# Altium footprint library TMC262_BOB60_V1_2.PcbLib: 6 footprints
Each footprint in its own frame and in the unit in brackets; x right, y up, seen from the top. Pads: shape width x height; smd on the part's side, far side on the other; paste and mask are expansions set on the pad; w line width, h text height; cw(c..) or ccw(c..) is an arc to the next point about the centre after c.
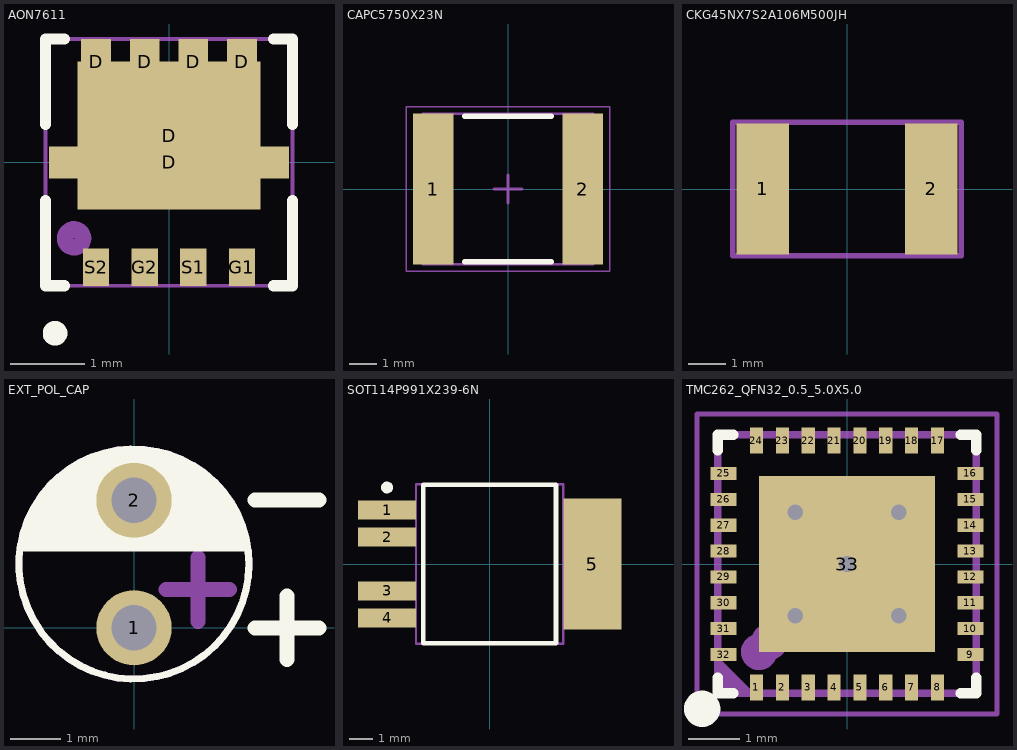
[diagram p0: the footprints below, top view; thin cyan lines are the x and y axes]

## AON7611 [mm]
pads (10):
  rect 0.4x0.6 smd mask+0.064: D(-0.975,1.35) D(-0.325,1.35) D(0.325,1.35) D(0.975,1.35)
  rect 3.21x0.43 smd: D(0,0)
  rect 2.45x1.98 smd: D(0,0.36)
  rect 0.35x0.5 smd mask+0.064: G1(0.975,-1.4) G2(-0.325,-1.4) S1(0.325,-1.4) S2(-0.975,-1.4)
Top Overlay:
  circle w0.178: c-1.524,-2.286 r0.076
  lines w0.15: -1.651,-0.508 -1.651,-1.651 -1.397,-1.651 ; -1.651,0.508 -1.651,1.651 -1.397,1.651 ; 1.397,-1.651 1.651,-1.651 1.651,-0.508 ; 1.397,1.651 1.651,1.651 1.651,0.508
TopAsm:
  circle w0.22: c-1.27,-1.016 r0.12
  lines w0.051: -1.651,-1.651 -1.651,0 -1.651,1.651 0,1.651 1.651,1.651 1.651,0 1.651,-1.651 0,-1.651 -1.651,-1.651
  text ".Designator" at -1.27,-0.254 h0.51
3D body: height 0.9, standoff 0, extent -1.55,-1.55 1.55,1.55

## CAPC5750X23N [mm] "Chip Capacitor, 2-Leads, Body 5,70x5,00mm, IPC Medium Density"
height 2.3
pads (2):
  rect 1.45x5.4 smd: 1(-2.675,0) 2(2.675,0)
Top Overlay:
  lines w0.2: -1.55,-2.6 1.55,-2.6 ; -1.55,2.6 1.55,2.6
Mechanical 15:
  lines w0.05: -3.65,-2.95 3.65,-2.95 3.65,2.95 -3.65,2.95 -3.65,-2.95
  lines w0.1: -0.5,0 0.5,0 ; 0,-0.5 0,0.5
Mechanical 16:
  lines w0.1: -3.05,-2.7 3.05,-2.7 3.05,2.7 -3.05,2.7 -3.05,-2.7
3D body "CAPC5750X23N.step": height 2.3, standoff 0, extent -3.05,-2.7 3.05,2.7

## CKG45NX7S2A106M500JH [mm] "1812 STACKED capacitor"
pads (2):
  rect 1.4x3.5 smd: 1(-2.25,0) 2(2.25,0)
TopAsm:
  lines w0.14: -3.048,-1.778 3.048,-1.778 3.048,1.778 -3.048,1.778 -3.048,-1.778
  text ".Designator" at -2,-0.5 h1
3D body: height 0.25, standoff 0, extent 1.652,-1.6 2.412,1.6
3D body: height 0.25, standoff 0, extent -2.412,-1.6 -1.652,1.6
3D body: height 3.35, standoff 0, extent -2.5,-1.6 -2.25,1.6
3D body: height 3.35, standoff 0, extent 2.25,-1.6 2.5,1.6
3D body "User Library-SMD CAPACITOR(1).step": height 1.8, standoff 0.8, extent -2.25,-1.6 2.25,1.6
3D body "User Library-SMD CAPACITOR(1).step": height 3.3, standoff 2.3, extent -2.25,-1.6 2.25,1.6

## EXT_POL_CAP [mm]
pads (2):
  round 1.5 hole 0.9: 1(0,0) 2(0,2.54)
Top Overlay:
  circle w0.14: c0,1.27 r2.29
  region: 0,1.524 -2.272,1.524 -2.249,1.732 -2.128,2.132 -1.936,2.504 -1.68,2.834 -1.368,3.113 -1.011,3.331 -0.62,3.48 -0.209,3.556 0,3.556 0.209,3.556 0.62,3.48 1.011,3.331 1.368,3.113 1.68,2.834 1.936,2.504 2.128,2.132 2.249,1.732 2.272,1.524 0,1.524 0,1.651 0.087,1.655 0.258,1.689 0.419,1.756 0.564,1.853 0.687,1.976 0.784,2.121 0.851,2.282 0.885,2.453 0.889,2.54 0.885,2.627 0.851,2.798 0.784,2.959 0.687,3.104 0.564,3.227 0.419,3.324 0.258,3.391 0.087,3.425 0,3.429 -0.087,3.425 -0.258,3.391 -0.419,3.324 -0.564,3.227 -0.687,3.104 -0.784,2.959 -0.851,2.798 -0.885,2.627 -0.889,2.54 -0.885,2.453 -0.851,2.282 -0.784,2.121 -0.687,1.976 -0.564,1.853 -0.419,1.756 -0.258,1.689 -0.087,1.655 0,1.651
  pour cut-out: 0.889,2.54 0.889,2.628 0.855,2.799 0.788,2.961 0.691,3.107 0.567,3.231 0.421,3.328 0.259,3.395 0.088,3.429 0,3.429 -0.088,3.429 -0.259,3.395 -0.421,3.328 -0.567,3.231 -0.691,3.107 -0.788,2.961 -0.855,2.799 -0.889,2.628 -0.889,2.54 -0.889,2.452 -0.855,2.281 -0.788,2.119 -0.691,1.973 -0.567,1.849 -0.421,1.752 -0.259,1.685 -0.088,1.651 0,1.651 0.088,1.651 0.259,1.685 0.421,1.752 0.567,1.849 0.691,1.973 0.788,2.119 0.855,2.281 0.889,2.452
  lines w0.3: 2.413,0 3.683,0 ; 2.413,2.54 3.683,2.54 ; 3.048,-0.635 3.048,0.635
TopAsm:
  circle w0.14: c0,1.27 r2.29
  region: -2.254,1.651 2.258,1.651 2.224,1.849 2.089,2.228 1.89,2.577 1.633,2.886 1.326,3.146 0.978,3.348 0.6,3.486 0.205,3.556 0.004,3.556 -0.198,3.556 -0.594,3.486 -0.972,3.348 -1.32,3.146 -1.627,2.887 -1.885,2.578 -2.085,2.228 -2.22,1.849
  lines w0.3: 0.635,0.762 1.905,0.762 ; 1.27,0.127 1.27,1.397
  text ".Designator" at -1.905,0.762 h1.27

## SOT114P991X239-6N [mm] "SOT223, 6-Leads, Body 6,54x9,91mm (avg), Pitch 1,14mm, IPC Medium Density"
height 2.39
pads (5):
  rect 2.45x0.8 smd: 1(-4.335,2.28) 2(-4.335,1.14) 3(-4.335,-1.14) 4(-4.335,-2.28)
  rect 2.45x5.55 smd: 5(4.335,0)
Top Overlay:
  circle w0.25: c-4.335,3.23 r0.125
  lines w0.2: -2.8,-3.35 -2.8,3.35 2.8,3.35 2.8,-3.35 -2.8,-3.35
Mechanical 13:
  lines w0.1: -3.11,-3.365 -3.11,3.365 3.11,3.365 3.11,-3.365 -3.11,-3.365
TopAsm:
  lines w0.1: -3.11,-3.365 3.11,-3.365 3.11,3.365 -3.11,3.365 -3.11,-3.365
  text ".Designator" at -2,-0.5 h1.27
3D body "SW3dPS-PG-TO252-5-11-1.STEP": height 2.3, standoff 0, extent -4.8,-3.25 5.1,3.25

## TMC262_QFN32_0.5_5.0X5.0 [mm]
pads (33):
  rect 0.254x0.5 smd mask+0.046: 1(-1.75,-2.385) 2(-1.25,-2.385) 3(-0.75,-2.385) 4(-0.25,-2.385) 5(0.25,-2.385) 6(0.75,-2.385) 7(1.25,-2.385) 8(1.75,-2.385) 17(1.75,2.385) 18(1.25,2.385) 19(0.75,2.385) 20(0.25,2.385) 21(-0.25,2.385) 22(-0.75,2.385) 23(-1.25,2.385) 24(-1.75,2.385)
  rect 0.5x0.254 smd mask+0.046: 9(2.385,-1.75) 10(2.385,-1.25) 11(2.385,-0.75) 12(2.385,-0.25) 13(2.385,0.25) 14(2.385,0.75) 15(2.385,1.25) 16(2.385,1.75) 25(-2.385,1.75) 26(-2.385,1.25) 27(-2.385,0.75) 28(-2.385,0.25) 29(-2.385,-0.25) 30(-2.385,-0.75) 31(-2.385,-1.25) 32(-2.385,-1.75)
  rect 3.4x3.4 smd paste-254: 33(0,0)
via 1,-1 diameter 0.757 hole 0.3
via 1,1 diameter 0.757 hole 0.3
via -1,1 diameter 0.757 hole 0.3
via -1,-1 diameter 0.757 hole 0.3
via 0,0 diameter 0.757 hole 0.3
Top Overlay:
  circle w0.5: c-2.8,-2.8 r0.1
  lines w0.2: -2.5,-2.2 -2.5,-2.5 -2.2,-2.5 ; -2.5,2.2 -2.5,2.5 -2.2,2.5 ; 2.2,-2.5 2.5,-2.5 2.5,-2.2 ; 2.2,2.5 2.5,2.5 2.5,2.2
Top Paste:
  region: 0.254,1.524 1.524,1.524 1.524,0.254 0.254,0.254
  region: -1.524,1.524 -0.254,1.524 -0.254,0.254 -1.524,0.254
  region: -1.524,-0.254 -0.254,-0.254 -0.254,-1.524 -1.524,-1.524
  region: 0.254,-0.254 1.524,-0.254 1.524,-1.524 0.254,-1.524
Bottom Solder:
  region: -1.778,1.778 1.778,1.778 1.778,-1.778 -1.778,-1.778
Mechanical 13:
  circle w0.5: c-1.7,-1.7 r0.1
  lines w0.15: -2.5,-2.5 2.5,-2.5 2.5,2.5 -2.5,2.5 -2.5,-2.5
Mechanical 15:
  lines w0.1: -2.9,-2.9 2.9,-2.9 2.9,2.9 -2.9,2.9 -2.9,-2.9
TopAsm:
  circle w0.5: c-1.5,-1.5 r0.1
  region: -2.5,-1.794 -1.794,-2.5 -2.5,-2.5
  lines w0.076: -2.5,-2.5 -2.5,2.5 2.5,2.5 2.5,-2.5 -2.5,-2.5
  text ".Designator" at -2,-0.5 h1.27
3D body: height 0.9, standoff 0, extent -2.5,-2.5 2.5,2.5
